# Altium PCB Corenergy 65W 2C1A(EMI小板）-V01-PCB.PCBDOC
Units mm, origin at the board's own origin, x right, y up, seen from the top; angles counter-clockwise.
Board outline 87.3 x 91.75 mm, 2 copper layers (Top Layer, Bottom Layer), stack 0.325 mm thick; 9 components, 103 nets, 27 pads, 28 vias.
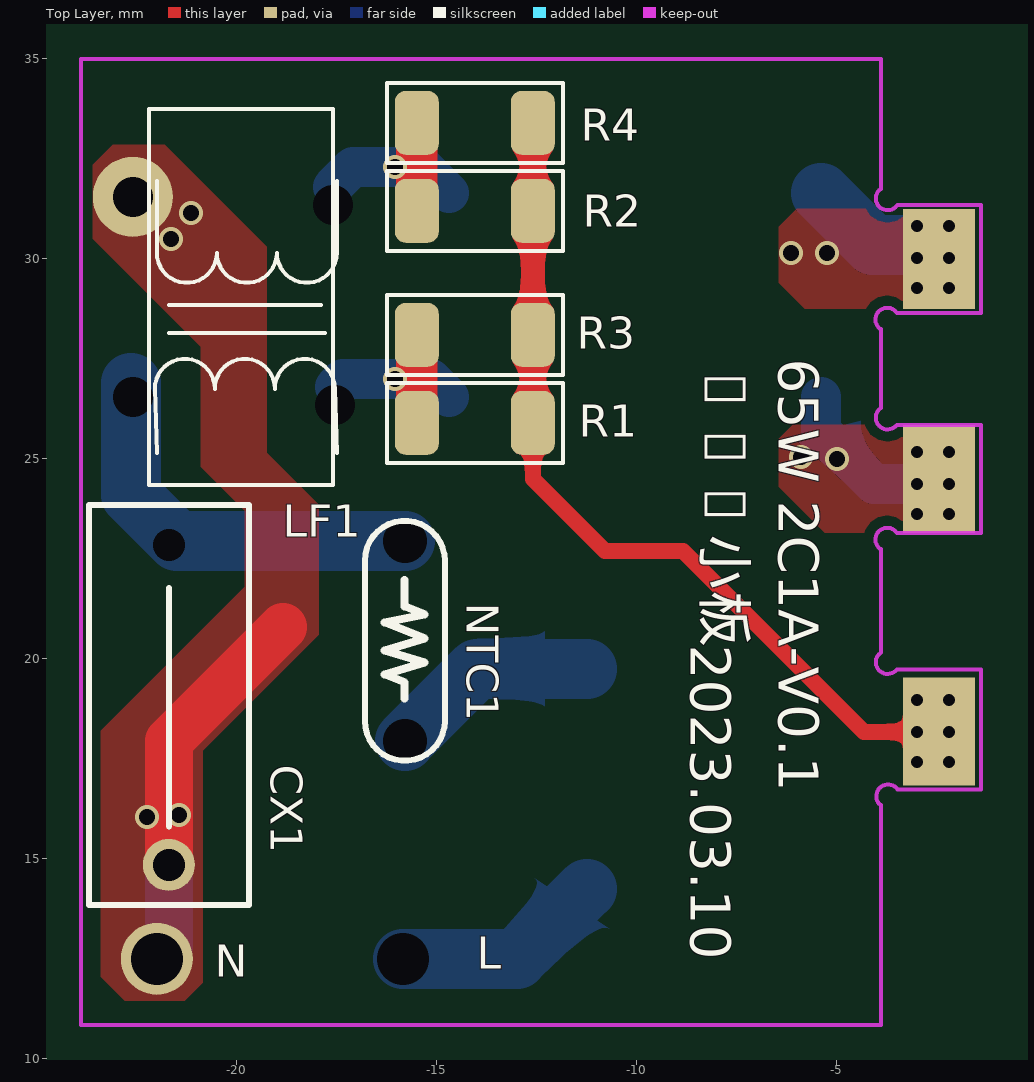
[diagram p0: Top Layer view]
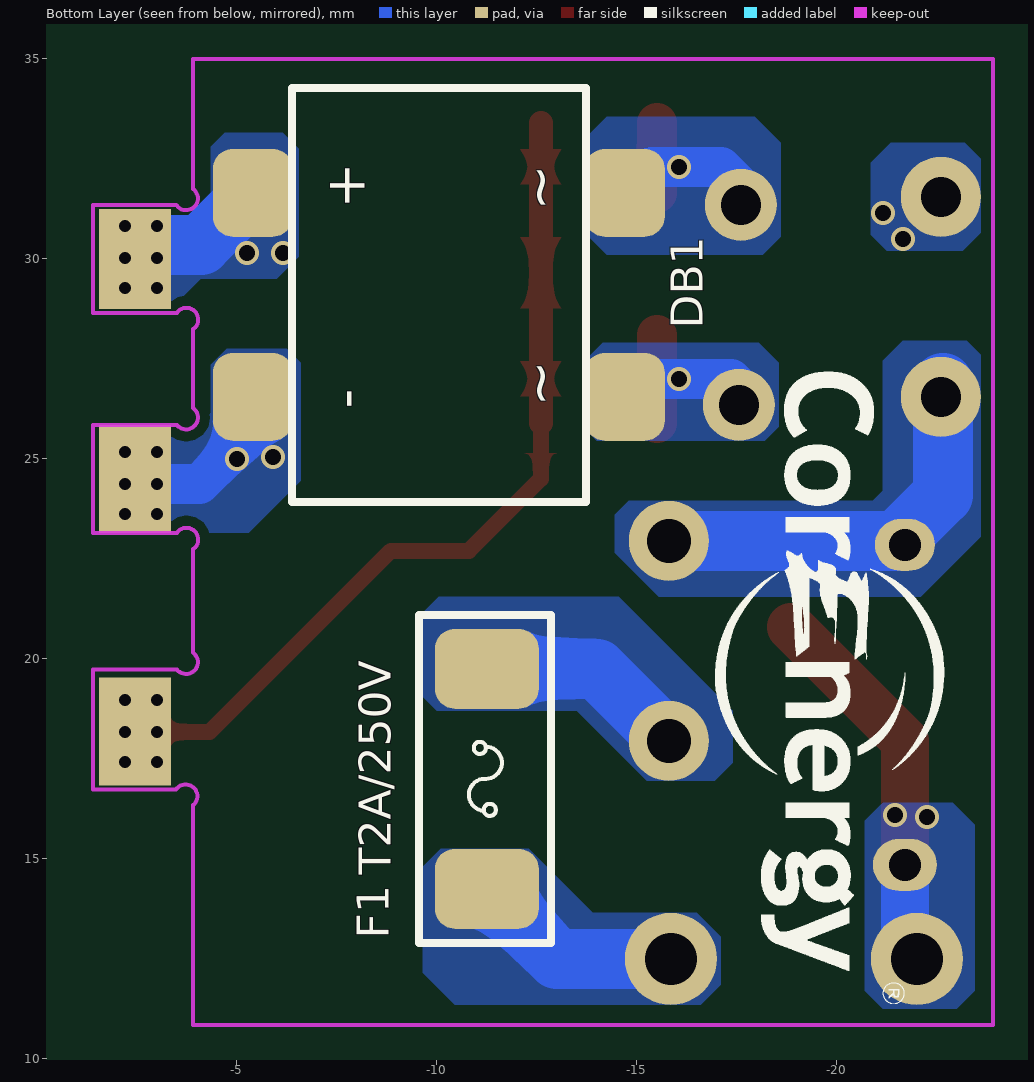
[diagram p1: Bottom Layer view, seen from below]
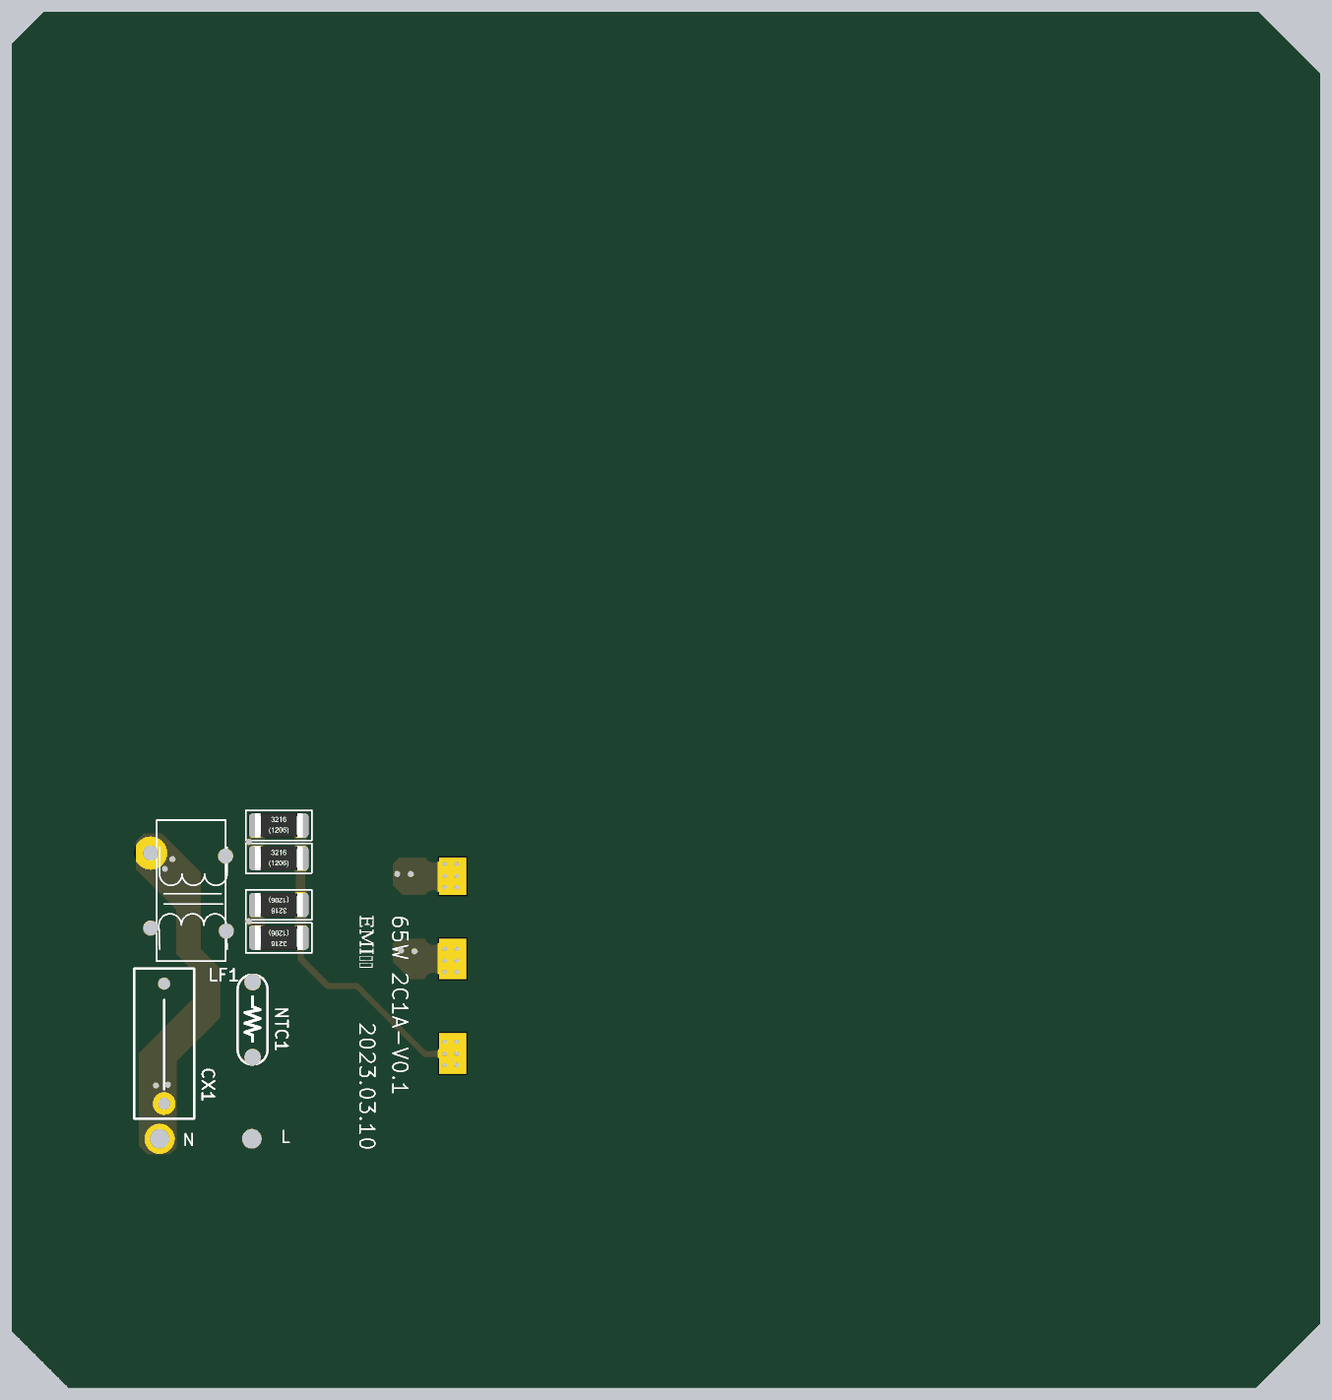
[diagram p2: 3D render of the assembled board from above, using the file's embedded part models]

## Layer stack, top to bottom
Top Layer: signal copper 0.0356
Dielectric: core 0.254, FR-4, Dk 4.2
Bottom Layer: signal copper 0.0356

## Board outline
-29.7,87.65 51.25,87.65 55.4,83.5 55.4,0.2 51.1,-4.1 -28.1,-4.1 -31.9,-0.3 -31.9,85.45 -29.95,87.4

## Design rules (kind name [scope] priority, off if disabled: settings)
Clearance Clearance_1 [InNet('GND') vs InNetClass('New Class')] p1: gap=1.5
Clearance [All] p2: gap=0.25
ComponentClearance [All] p1: gap=0 collisioncheckmode=3 verticalgap=0 showdistances=FALSE
FabricationTestpoint [(IsPad And (OnTopLayer Or OnBottomLayer))] p1: side=3 testpointundercomponent=TRUE minsize=1.016 maxsize=2.54 preferedsize=1.524 minholesize=0 maxholesize=1.016 preferedholesize=0.813 testpointgrid=0.025 allowsidetop=TRUE allowsidebottom=TRUE usegrid=TRUE gridtolerance=0
PolygonConnect [All] p1: connectstyle=Direct reliefconductorwidth=0.254 reliefentries=4 polygonreliefangle="90 Angle" airgapwidth=0.254
RoutingVias [All] p1: holewidth=0.3 width=0.5 viastyle="Through Hole" minholewidth=0.3 minwidth=0.5 maxholewidth=10 maxwidth=10
SilkToSolderMaskClearance SilkscreenOverComponentPads [IsPad] p1: minsilkscreentomaskgap=0.254 clearancetoexposedcopper=TRUE
SolderMaskExpansion [All] p1: expansion=0.102
Width [All] p1: maxlimit=10 minlimit=0.2 preferedwidth=0.4
25 further rules are at their usual default settings.

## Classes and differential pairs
net class "New Class": NetC27_1 NetC30_1 VH

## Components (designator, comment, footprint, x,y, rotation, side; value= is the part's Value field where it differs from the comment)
CX1 "0.22uF" CX_10*4_V -21.7,18.85 r180 top
DB1 "YBSM6008" BD-TBM -10.05,29.1 r90 bottom (schematic designator BD100)
F1 "T2A/250V" F-6125 -11.25,17 r90 bottom
LF1 "T6*3*3/100uH" T10*6*5 -19.9,28.45 r270 top
NTC1 "5D-3" NPTC-5-P5-L -15.8,20.45 r90 top
R1 "3.6M 1/2W" 1206(H) -14.05,25.9 r180 top
R2 "3.6M 1/2W" 1206(H) -14.05,31.2 r0 top
R3 "3.6M 1/2W" 1206(H) -14.05,28.1 r180 top
R4 "3.6M 1/2W" 1206(H) -14.05,33.4 r0 top

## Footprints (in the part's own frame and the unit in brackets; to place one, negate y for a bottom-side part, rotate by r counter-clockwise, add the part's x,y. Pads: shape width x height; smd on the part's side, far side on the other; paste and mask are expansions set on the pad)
1206(H) [mm]
  rrect50% 1.1x1.6 smd mask+0.03: 1(-1.45,0) 2(1.45,0)
  silkscreen extent -2.2,-1 2.2,1, body extent -1.6,-0.8 1.6,0.8, height 0.55
BD-TBM [mm]
  rrect50% 2.2x2 smd mask+0.03: 1(2.55,4.65) 2(2.55,-4.65) 3(-2.55,-4.65) 4(-2.55,4.65)
  silkscreen extent -5.18,-3.67 5.18,3.67
CX_10*4_V [mm]
  round 1.3 / inner round 1 / far side oval 1.6x1.3 hole 0.8: 1(0,4)
  round 0 / inner round 0.8 / far side oval 1.5x1.3 hole 0.8: 2(0,-4)
  silkscreen extent -2,-5 2,5
F-6125 [mm]
  rrect50% 2x2.6 smd mask+0.03: 1(-2.75,0) 2(2.75,0)
  silkscreen extent -4.1,-1.6 4.1,1.7
NPTC-5-P5-L [mm]
  round 0 / inner round 2 / far side round 2 hole 1.1: 1(-2.5,0) 2(2.5,0)
  silkscreen extent -3,-1 3,1
T10*6*5 [mm] "磁环电感"
  round 0 / inner round 1 / far side round 1.8 hole 1: 1(2.1,2.35)
  round 2 hole 1: 2(-3.1,-2.7)
  round 0 / inner round 1 / far side round 2 hole 1: 3(1.9,-2.7)
  round 0 / inner round 1.8 / far side round 1.8 hole 1: 4(-2.9,2.3)
  silkscreen extent -5.3,-2.3 4.1,2.4

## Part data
CX1: library part Cap, "Capacitor"
DB1: library part BRIDGE, "1000V/6A， YBS3,YANGJIE(扬杰)"
F1: library part FUSE, "FUSE"
LF1: library part L-T12*6*6
R1 R2 R3 R4: library part RESISTOR

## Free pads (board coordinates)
  round 1.8 / inner round 2.3 / far side round 2.3 hole 1.3: 3(-22,12.5)
  round 0 / inner round 2.3 / far side round 2.3 hole 1.3: 3(-15.85,12.5)
  rect 1.8x2.5 all layers, no hole: 7(-2.45,30)
  rect 1.8x2.7 all layers, no hole: 7(-2.45,24.5) 7(-2.449,18.188)

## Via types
v1: diameter 0.5, hole 0.3, Top Layer to Bottom Layer, 18 vias
v2: diameter 0.6, hole 0.4, Top Layer to Bottom Layer, tented both sides, 10 vias

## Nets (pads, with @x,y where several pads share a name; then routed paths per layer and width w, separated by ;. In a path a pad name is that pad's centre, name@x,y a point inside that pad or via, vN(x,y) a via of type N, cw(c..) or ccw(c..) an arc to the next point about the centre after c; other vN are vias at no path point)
$$$3: 
$$$11: 
$$$13: 
$$$16: 
$$$18: 
$$$20: 
$$$24: 
$$$27: 
$$$28: 
$$$29: 
$$$31: 
$$$32: 
$$$37: 
$$$39: 
$$$40: 
$$$43: 
$$$51: 
BST2: 
CC1: 
CC2: 
COMP2: 
DMA2: 
DMA2-R: 
DMC: 
DPA2-R: 
DPC: 
EN: 
FB-G: 
FB_IC: 
GND: DB1.4 pad.7@-2.45,24.5 | length 3.8
  Bottom Layer w1: DB1.4 -5.4,25.7 -4.072,24.372 v1(-3,24.372)
  other v1: -3,23.622 -2.2,23.622 -2.2,24.372 -3,25.172 -2.2,25.172
  other v2: -5,25 -5.9,25.05
HGATE2: 
L: 
LGATE2: 
N: 
NetC5_1: 
NetC10_1: 
NetC21_1: 
NetC21_2: 
NetC22_2: 
NetC24_1: 
NetC26_1: 
NetC27_1: 
NetC28_1: 
NetC29_2: 
NetC30_1: 
NetC30_2: 
NetC32_1: 
NetC33_1: 
NetC35_2: 
NetCX1_1: CX1.1 LF1.2 pad.3@-22,12.5 | length 9.3
  Top Layer w1.2: CX1.1@-21.7,15.15 -21.7,17.95 -18.85,20.8
  Bottom Layer w1.2: pad.3@-22,12.5 -21.7,12.8 CX1.1
  other v2: -22.25,16.05 -21.45,16.1 -21.65,30.5 -21.15,31.15
NetCX1_2: CX1.2 LF1.3 NTC1.2 | length 10.1
  Bottom Layer w1.5: LF1.3@-22.65,26.9 -22.65,24.1 -21.5,22.95 NTC1.2
NetD2_1: 
NetD2_2: 
NetD3_1: 
NetD3_2: 
NetD4_2: 
NetDB1_1: DB1.2 LF1.4 R2.1 R4.1 | length 5.1
  Top Layer w1: R2.1@-15.5,31.65 R4.1
  Bottom Layer w1: LF1.4@-17.6,31.8 -17.1,32.3 v2(-16.05,32.3) -15.35,32.3 DB1.2
NetDB1_2: DB1.3 LF1.1 R1.2 R3.2 | length 5.3
  Top Layer w1: R1.2 R3.2
  Bottom Layer w1: LF1.1@-17.55,26.8 -17.35,27 v2(-16.05,27) -15.15,27 DB1.3
NetDB1_4: DB1.1 pad.7@-2.45,30 | length 3.1
  Bottom Layer w1.5: DB1.1 -4.1,30.35 pad.7@-2.8,30.35
  other v1: -3,29.272 -2.2,29.272 -3,30.022 -2.2,30.022 -3,30.822 -2.2,30.822
  other v2: -6.15,30.15 -5.25,30.15
NetEC8_1: 
NetF1_1: F1.1 pad.3@-15.85,12.5 | length 5.3
  Bottom Layer w1.5: pad.3@-15.85,12.5 -13,12.5 F1.1
NetFB100_1: 
NetNTC1_1: F1.2 NTC1.1 | length 5.3
  Bottom Layer w1.5: NTC1.1 -14,19.75 F1.2
NetQ8_2: 
NetQ8_3: 
NetQ9_D: 
NetQ9_G: 
NetQ11_1: 
NetR1_1: pad.7@-2.449,18.188 R1.1 R2.2 R3.1 R4.2 | length 21.1
  Top Layer w0.4: R1.1 -12.6,24.5 -10.8,22.7 -8.85,22.7 -4.322,18.172 v1(-3,18.172)
  Top Layer w0.6: R1.1 R3.1 R2.2 R4.2
  other v1: -3,17.422 -2.2,17.422 -2.2,18.172 -3,18.972 -2.2,18.972
NetR2_2: 
NetR46_1: 
NetR52_1: 
NewNet1: 
NewNet01: 
NewNet2: 
NewNet03: 
NewNet04: 
NewNet4: 
NewNet5: 
NewNet05: 
NewNet6: 
NewNet7: 
NewNet8: 
NewNet9: 
NewNet10: 
NewNet11: 
NewNet12: 
NewNet13: 
NewNet14: 
NewNet15: 
NewNet16: 
NewNet22: 
PLUG: 
PLUGA: 
SCK: 
SDA: 
SGND: 
SW2: 
V+: 
VCC: 
VDD1: 
VDD2: 
VH: 

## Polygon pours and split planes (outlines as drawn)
NetF1_1 on Bottom Layer "Keep-Out Layer-No Net" (solid, remove dead copper, pour order 116): -11.35,15.25 -10.1,15.25 -9.65,14.8 -9.65,12.15 -10.45,11.35 -16.6,11.35 -17.1,11.85 -17.1,13.05 -16.55,13.6 -16.5,13.65 -15.7,13.65 -13.9,13.65 -12.3,15.25 -11.95,15.25
NetNTC1_1 on Bottom Layer "Keep-Out Layer-No Net" (solid, remove dead copper, pour order 118): -10.05,21.55 -9.5,21 -9.5,19.2 -10,18.7 -13.5,18.7 -15.25,16.95 -16.95,16.95 -17.4,17.4 -17.4,18.7 -14.55,21.55
NetCX1_2 on Bottom Layer "Keep-Out Layer-No Net" (solid, remove dead copper, pour order 119): -22.85,27.95 -21.65,27.95 -21.15,27.45 -21.15,24.2 -20.9,23.95 -14.8,23.95 -14.45,23.6 -14.45,22.65 -15.25,21.85 -15.55,21.55 -21.4,21.55 -22.1,21.55 -23.4,22.85 -23.6,23.05 -23.6,26.45 -23.6,27.6 -23.25,27.95
NetCX1_1 on Bottom Layer "Keep-Out Layer-No Net" (solid, remove dead copper, pour order 121): -22,16.4 -21.15,16.4 -20.85,16.1 -20.7,15.95 -20.7,13.1 -20.7,11.7 -21.15,11.25 -23,11.25 -23.45,11.7 -23.45,15.85 -22.9,16.4
NetCX1_1 on Bottom Layer "Keep-Out Layer-No Net" (solid, remove dead copper, pour order 123): -22.8,32.9 -21.35,32.9 -20.85,32.4 -20.85,30.6 -21.2,30.25 -21.25,30.2 -21.75,30.2 -23.15,30.2 -23.6,30.65 -23.6,32.5 -23.2,32.9
NetDB1_1 on Bottom Layer "Keep-Out Layer-No Net" (solid, remove dead copper, pour order 125): -16.6,33.55 -14.25,33.55 -13.7,33 -13.7,30.65 -14.25,30.1 -18.15,30.1 -18.6,30.55 -18.6,32.9 -18,33.5 -17.95,33.55 -17.1,33.55
NetDB1_2 on Bottom Layer "Keep-Out Layer-No Net" (solid, remove dead copper, pour order 126): -14.15,27.9 -13.7,27.45 -13.7,25.75 -14,25.45 -18.2,25.45 -18.55,25.8 -18.55,27.4 -18.05,27.9
NetDB1_4 on Bottom Layer "Keep-Out Layer-No Net" (solid, remove dead copper, pour order 127): -4.7,33.15 -4.35,32.8 -4.35,31.55 -4.05,31.25 -2.9,31.25 -2.9,28.75 -3.35,28.75 -4.1,29.5 -6,29.5 -6.55,30.05 -6.55,32.75 -6.15,33.15
GND on Bottom Layer "Keep-Out Layer-No Net" (solid, remove dead copper, pour order 128): -5.75,27.75 -4.75,27.75 -4.35,27.35 -4.35,26.55 -4.35,26.15 -4.15,25.95 -4.05,25.85 -2.5,25.85 -2.5,23.2 -2.55,23.15 -5.3,23.15 -6.2,24.05 -6.6,24.45 -6.6,25.2 -6.6,27.4 -6.25,27.75
GND on Top Layer "Keep-Out Layer-No Net" (solid, remove dead copper, pour order 129): -5.9,25.85 -2.4,25.85 -2.5,25.75 -2.5,23.15 -5.3,23.15 -6.25,24.1 -6.45,24.3 -6.45,24.85 -6.45,25.5 -6.1,25.85
NetDB1_4 on Top Layer "Keep-Out Layer-No Net" (solid, remove dead copper, pour order 130): -3.7,31.25 -2.75,31.25 -2.75,28.8 -2.8,28.75 -5.8,28.75 -6.45,29.4 -6.45,30.8 -6.05,31.2 -6,31.25 -4.25,31.25
NetCX1_1 on Top Layer "Keep-Out Layer-No Net" (solid, remove dead copper, pour order 131): -21.8,32.85 -19.25,30.3 -19.25,25.15 -17.95,23.85 -17.95,20.6 -20.85,17.7 -20.85,11.9 -21.3,11.45 -22.8,11.45 -23.4,12.05 -23.4,18.2 -19.8,21.8 -19.8,23.7 -20.9,24.8 -20.9,27.8 -23.6,30.5 -23.6,32.35 -23.1,32.85

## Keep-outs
Keep-Out Layer:
  lines w0.1: -3.921,22.749 cw(c-3.741,22.981) -3.5,23.15 -1.4,23.15 -1.4,25.85 -3.5,25.85 cw(c-3.732,26.03) -3.901,26.271 ; -3.921,28.249 cw(c-3.741,28.481) -3.5,28.65 ; -3.9,16.35 -3.9,10.85 -23.9,10.85 -23.9,35 -3.9,35 -3.9,31.75 ccw(c-3.731,31.509) -3.499,31.329 ; -3.9,22.749 -3.9,20.155 ccw(c-3.731,19.915) -3.499,19.735 -1.399,19.735 -1.399,16.735 -3.478,16.735 ccw(c-3.719,16.566) -3.899,16.333 ; -3.9,26.3 -3.9,28.249 ; -3.477,31.35 -1.4,31.35 -1.4,28.65 -3.472,28.65

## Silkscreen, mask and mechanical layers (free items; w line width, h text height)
Top Overlay:
  text "65W 2C1A-V0.1" at -6.45,27.5 h1 r270
  text "EMI小板" at -8.65,27.45 h1.8 r270
  text "2023.03.10" at -8.65,20.35 h1 r270
  text "L" at -14,12.25 h0.8
  text "N" at -20.55,12.05 h0.8
Bottom Overlay:
  drawing of 4132 lines, arcs and shapes, not listed
Mechanical 2:
  circle w0.12: c-8.9,33.05 r5
  lines w0.1: -15.95,28.05 -5.4,28.05 ; -13.9,5.25 -13.9,38 ; -12.45,28.05 -12.45,29.55 ; -4.4,10.5 -4.4,35
  lines w1.6: -6.5,28.6 -4.45,28.6 -3.1,27.25 -1.15,27.25
  lines w3.2: -19.45,8.85 -18.95,9.35 -18.95,13.55 -17.2,15.3 -14.55,15.3 -12.85,17 -9.45,17 -7.05,14.6
  text "板厚1.0mm  2OZ   2层板" at -23.15,38.25 h2
Drill Drawing:
  text ".legend" at -33.95,38.3 h1.52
